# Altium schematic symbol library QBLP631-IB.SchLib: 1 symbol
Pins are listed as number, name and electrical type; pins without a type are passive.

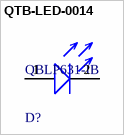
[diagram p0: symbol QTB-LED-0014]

## QTB-LED-0014
designator D?, comment QBLP631-IB
LED BLUE CLEAR 0805 SMD; Manufacturer: QT Brightek (QTB); Lens Size: 1.25mm; Luminous Intensity: 125mcd; Test Current: 20mA; Lens Color: Colorless; Lens Style: Flat; Forward Voltage: 3.1V; Wavelength - Dominant: 470nm
footprint QBLP631-IB
pins: 1 ANODE (+), 2 CATHODE (-)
